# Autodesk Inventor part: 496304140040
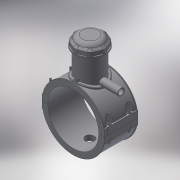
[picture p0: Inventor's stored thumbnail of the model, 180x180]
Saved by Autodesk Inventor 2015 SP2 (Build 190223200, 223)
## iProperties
Created: 2017-07
Part Number: 496304140040
Material: Generic
Description: PLASSON TAPPING SADDLE 140x40
Document SubType Name: Modeling
Designer: KIM
Mass: 942.785 g
Surface Area: 2280.08 cm^2
Volume: 942.785 cm^3
Density: 1 g/cm^3
Appearance: Default
Author: KIM
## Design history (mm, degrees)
derived "496304.ipt"
feature "Solid1::496304.ipt"
feature "Solid2::496304.ipt"
feature "Solid4::496304.ipt"
feature "Solid5::496304.ipt"
tag "TaggingFeature1"
body "Solid1"
body "Solid2"
other parameters: "d3" = 35, "d4" = 118, "d5" = 0, "d6" = 0.1, "d8" = 0, "d19" = 6, "d20" = 6, "d21" = 70.8, "d23" = 0, "d24" = 35.4, "d26" = 0, "d29" = 3, "d30" = 46.66667, "d31" = 6, "d32" = 0, "d33" = 0, "d34" = 0.6, "d40" = 82.992, "d43" = 0, "d45" = 0, "d47" = 150.6, "d70" = 15, "d72" = 0, "d73" = 6, "d75" = 5, "d76" = 0, "d77" = 7, "d79" = 15, "d80" = 47.2, "d82" = 5 deg, "d84" = 4, "d85" = 14, "d86" = 0, "d87" = 3, "d88" = 0, "d89" = 1, "d90" = 1, "d91" = 94.4, "d92" = 0, "d93" = 0.5, "d94" = 73.68421, "d96" = 162.792, "d97" = 2.36, "d98" = 0, "d102" = 1.4, "d120" = 140 deg, "d121" = 24.228, "d122" = 20 deg, "d123" = 319.2, "d124" = 95.76, "d126" = 0, "d143" = 144.2, "d145" = 15.07692, "d149" = 2.1, "d150" = 16.58462, "d153" = 118, "d154" = 0, "d156" = 79.8, "d157" = 160 deg, "d159" = 3.92, "d161" = 2.1, "d162" = 70.8, "d163" = 0, "d167" = 14, "d168" = 77.85366, "d170" = 3.375, "d172" = 0, "d173" = 1, "d176" = 20 deg, "d177" = 9.8, "d178" = 19.6, "d180" = 0, "d183" = 7.84, "d184" = 7.84, "d185" = 38.35, "d186" = 38.35, "d187" = 79.8, "d188" = 5.88, "d189" = 9.8, "d190" = 0, "d191" = 119.7, "d193" = 6.3, "d194" = 4.13, "d195" = 90 deg, "d197" = 0, "d199" = 0, "d200" = 9.8, "d202" = 0, "d203" = 177, "d204" = 66.5, "d205" = 49, "d206" = 59.5, "d207" = 132.75, "d208" = 138.06, "d209" = 164.61, "d210" = 60.2, "d212" = 56, "d213" = 36, "d216" = 0, "d217" = 14, "d218" = 14, "d219" = 2.8, "d224" = 0, "d230" = 5.6, "d233" = 6, "d237" = 35.4, "d238" = 6.02433, "d240" = 35.4, "d241" = 35.4, "d242" = 35.4, "d243" = 6, "d244" = 35.4, "d245" = 35.4, "d246" = 35.4, "d247" = 6, "d248" = 6, "d249" = 6, "d251" = 35.4, "d253" = 6, "d254" = 6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
